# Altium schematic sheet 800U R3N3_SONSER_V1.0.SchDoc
size A4
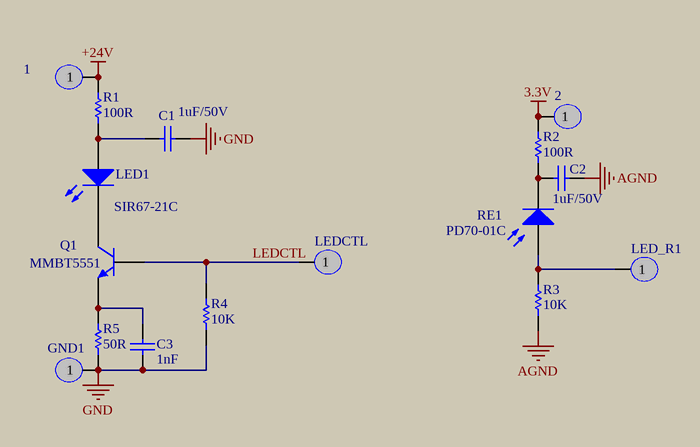
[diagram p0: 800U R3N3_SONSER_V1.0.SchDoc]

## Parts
1  (no value)  [HOLE_SMD]
2  (no value)  [HOLE_SMD]
C1  value 1uF/50V  [C0805]  (hidden comment: 105)
C2  value 1uF/50V  [C0603]  (hidden comment: 105)
C3  value 1nF  [C0603]  (hidden comment: 102)
GND1  (no value)  [HOLE_SMD]
LED1  SIR67-21C  [LED-3.5X2.8]
LED_R1  (no value)  [HOLE_SMD]
LEDCTL  (no value)  [HOLE_SMD]
Q1  MMBT5551  [SOT-23]
R1  value 100R  [R0805]  (hidden comment: 100)
R2  value 100R  [R0805]  (hidden comment: 100)
R3  10K  [R0603]
R4  10K  [R0603]
R5  value 50R  [R0805]  (hidden comment: 15)
RE1  PD70-01C  [LED9*4]

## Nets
3.3V: 2.1 R2.2
+24V: 1.1 R1.2
AGND: C2.2 R3.1
GND: C1.2 C3.2 GND1.1 R4.1 R5.1
LEDCTL: LEDCTL.1 Q1.1(B) R4.2
NetC1_1: C1.1 LED1.1(A) R1.1
NetC2_1: C2.1 R2.1 RE1.2(K)
NetC3_1: C3.1 Q1.2(E) R5.2
NetLED1_2: LED1.2(K) Q1.3(C)
NetLED_R1_1: LED_R1.1 R3.2 RE1.1(A)

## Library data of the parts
1 2 GND1 LED_R1 LEDCTL = 焊盘
C1-C3 = Cap: 贴片电容
LED1 = LED0: 贴片红外发射管
Q1 = NPN: 贴片NPN三极管
R1-R5 = Res Semi: 贴片电阻
RE1 = Photo Sen: 贴片接收管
